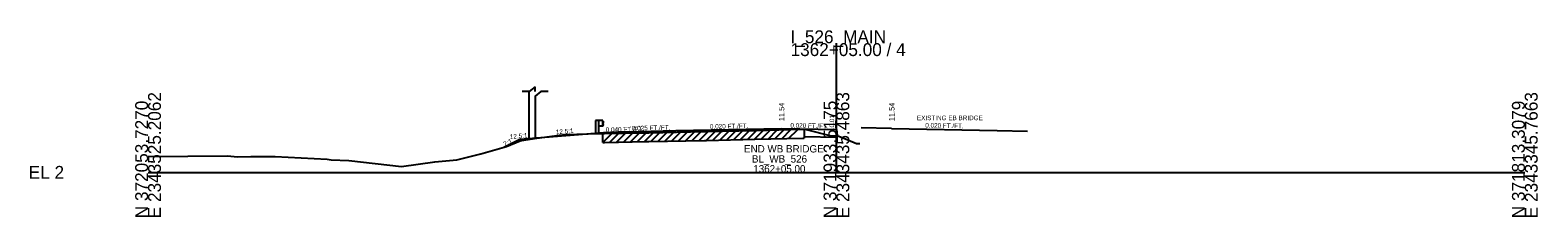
# Model space of a CAD drawing. Extents: x -170 to 2527928, y -10 to 1619750.
# Drawn here: x -25.7 to 302.8, y 7490.3 to 7531 of the extents above; entities that cross this region are included whole.
import ezdxf

# ---------------------------------------------------------------- set-up
doc = ezdxf.new("R2010")
doc.units = 0
for name, color, linetype in [('Default', 7, 'Continuous'), ('RD_GPK_XS_Cell', 7, 'Continuous'), ('RD_PD_NOISE-WALL-GM', 7, 'Continuous'), ('RD_PD_WallFill', 7, 'Continuous'), ('RD_XS_Base', 7, 'Continuous'), ('RD_XS_Bridge', 7, 'Continuous'), ('RD_XS_EarthShd', 7, 'Continuous'), ('RD_XS_ExGround', 7, 'Continuous'), ('RD_XS_ExPaveRet', 7, 'Continuous'), ('RD_XS_GR', 7, 'Continuous'), ('RD_XS_Pave', 7, 'Continuous'), ('RD_XS_PaveShd', 7, 'Continuous'), ('RD_XS_TieSlope', 7, 'Continuous'), ('RD_XS_TX_Elev_EX', 7, 'Continuous'), ('RD_XS_TX_Slope', 7, 'Continuous'), ('RD_XS_TX_Station', 7, 'Continuous')]:
    doc.layers.add(name, color=color, linetype=linetype)

msp = doc.modelspace()

# ---------------------------------------------------------------- linework, layer by layer
at = {"layer": 'Default'}
for p, q in [((83.08, 7517.63), (81.49, 7517.63)), ((84.33, 7518.66), (83.08, 7517.63)), ((84.33, 7517.63), (84.33, 7518.66)), ((85.58, 7517.63), (84.33, 7516.6)), ((87.17, 7517.63), (85.58, 7517.63))]:
    msp.add_line(p, q, dxfattribs=at)
at = {"layer": 'RD_GPK_XS_Cell'}
for p, q in [((150, 7500), (150, 7528.13)), ((0, 7500), (150, 7500)), ((150, 7500), (300, 7500))]:
    msp.add_line(p, q, dxfattribs=at)
at = {"layer": 'RD_PD_NOISE-WALL-GM'}
for p, q in [((82.95, 7517.63), (82.95, 7507.31)), ((84.45, 7507.43), (84.45, 7516.7))]:
    msp.add_line(p, q, dxfattribs=at)
at = {"layer": 'RD_PD_WallFill'}
msp.add_line((150, 7509.3), (150.18, 7508.02), dxfattribs=at)
at = {"layer": 'RD_XS_Base'}
for p, q in [((99.27, 7508.44), (99.27, 7508.62)), ((143, 7507.8), (150, 7507.66)), ((150, 7507.66), (150, 7509.3))]:
    msp.add_line(p, q, dxfattribs=at)
at = {"layer": 'RD_XS_Bridge'}
for p, q in [((162, 7509.54), (155.36, 7509.67)), ((162, 7509.54), (185, 7509.08)), ((185, 7509.08), (191.64, 7508.95))]:
    msp.add_line(p, q, dxfattribs=at)
at = {"layer": 'RD_XS_EarthShd'}
msp.add_line((99.27, 7508.62), (80.99, 7507.15), dxfattribs=at)
at = {"layer": 'RD_XS_ExGround'}
msp.add_lwpolyline([(0, 7503.46), (17.31, 7503.59), (19.49, 7503.41), (22.42, 7503.44), (24.23, 7503.47), (27.68, 7503.44), (39.06, 7502.86), (39.9, 7502.69), (43.77, 7502.58), (55.24, 7501.28), (62.48, 7502.27), (67.29, 7502.7), (72.49, 7504), (78.13, 7505.6), (81.07, 7506.86), (81.89, 7506.98), (84.72, 7507.47), (89.65, 7508.13), (90.96, 7508.21), (98.39, 7508.45), (99.09, 7508.44), (99.43, 7508.45), (108.54, 7508.61), (109.1, 7508.62), (121.24, 7508.87), (121.66, 7508.88), (132.22, 7509.1), (142.71, 7509.37), (143, 7509.38), (143.4, 7509.33), (148.84, 7507.96), (150.18, 7508.02), (152.46, 7507.08), (154.34, 7506.27), (154.89, 7506.31), (155.13, 7506.29)], dxfattribs=at)
at = {"layer": 'RD_XS_ExPaveRet'}
for p, q in [((99.09, 7506.52), (101.04, 7508.47)), ((99.09, 7506.52), (99.09, 7508.44)), ((100.59, 7506.55), (102.55, 7508.5)), ((102.09, 7506.58), (104.05, 7508.53)), ((103.59, 7506.6), (105.55, 7508.55)), ((105.09, 7506.63), (107.05, 7508.58)), ((106.59, 7506.66), (108.55, 7508.61)), ((108.09, 7506.68), (110.05, 7508.64)), ((109.59, 7506.71), (111.55, 7508.67)), ((111.09, 7506.74), (113.05, 7508.7)), ((112.59, 7506.77), (114.55, 7508.73)), ((114.09, 7506.81), (116.05, 7508.76)), ((115.59, 7506.84), (117.55, 7508.79)), ((117.09, 7506.87), (119.05, 7508.83)), ((118.59, 7506.9), (120.55, 7508.86)), ((120.09, 7506.93), (122.05, 7508.89)), ((121.59, 7506.96), (123.55, 7508.92)), ((121.66, 7506.96), (132.22, 7507.19)), ((123.09, 7506.99), (125.05, 7508.95)), ((124.59, 7507.03), (126.55, 7508.98)), ((126.09, 7507.06), (128.05, 7509.02)), ((127.59, 7507.09), (129.55, 7509.05)), ((129.09, 7507.12), (131.05, 7509.08)), ((130.59, 7507.15), (132.55, 7509.11)), ((132.09, 7507.18), (134.06, 7509.15)), ((132.22, 7507.19), (142.71, 7507.45)), ((133.59, 7507.22), (135.56, 7509.19)), ((135.09, 7507.26), (137.06, 7509.23)), ((136.59, 7507.3), (138.56, 7509.26)), ((138.09, 7507.33), (140.06, 7509.3)), ((139.59, 7507.37), (141.56, 7509.34)), ((142.71, 7507.45), (143, 7507.46)), ((143, 7509.38), (143, 7507.46)), ((99.09, 7506.52), (99.43, 7506.53)), ((99.43, 7506.53), (108.54, 7506.69)), ((108.54, 7506.69), (109.1, 7506.7)), ((109.1, 7506.7), (121.24, 7506.96)), ((121.24, 7506.96), (121.66, 7506.96))]:
    msp.add_line(p, q, dxfattribs=at)
at = {"layer": 'RD_XS_GR'}
for p, q in [((98.18, 7511.26), (97.51, 7511.26)), ((97.51, 7511.26), (97.51, 7508.46)), ((99.09, 7511.26), (98.18, 7511.26)), ((98.18, 7511.26), (98.18, 7508.51)), ((99.09, 7510.09), (99.09, 7511.26)), ((99.09, 7511.18), (99.26, 7510.98)), ((99.26, 7510.93), (99.09, 7510.73)), ((99.26, 7510.41), (99.09, 7510.61)), ((99.09, 7510.16), (99.26, 7510.36)), ((99.26, 7510.98), (99.26, 7510.93)), ((99.26, 7510.36), (99.26, 7510.41)), ((99.09, 7510.09), (98.18, 7510.09))]:
    msp.add_line(p, q, dxfattribs=at)
at = {"layer": 'RD_XS_Pave'}
for p, q in [((104, 7508.8), (115, 7509.08)), ((115, 7509.08), (138, 7509.54))]:
    msp.add_line(p, q, dxfattribs=at)
at = {"layer": 'RD_XS_PaveShd'}
msp.add_line((138, 7509.54), (150, 7509.3), dxfattribs=at)
msp.add_lwpolyline([(104, 7508.8), (99.27, 7508.62)], dxfattribs=at)
at = {"layer": 'RD_XS_TieSlope'}
for p, q in [((80.99, 7507.15), (77.56, 7505.44)), ((150, 7509.3), (150, 7508.01))]:
    msp.add_line(p, q, dxfattribs=at)

# ---------------------------------------------------------------- texts
at = {"layer": 'RD_GPK_XS_Cell'}
for s, p in [('I_526_MAIN', (140, 7528.13)), ('1362+05.00 / 4', (140, 7525.33)), ('EL 2', (-26, 7498.6))]:
    msp.add_text(s, height=2.8, dxfattribs=at).set_placement(p)
for s, p in [('E 2343525.2062', (2.8, 7490)), ('E 2343435.4863', (152.8, 7490)), ('E 2343345.7663', (302.8, 7490)), ('N 372053.7270', (0, 7490)), ('N 371933.5175', (150, 7490)), ('N 371813.3079', (300, 7490))]:
    msp.add_text(s, height=2.8, rotation=90, dxfattribs=at).set_placement(p)
at = {"layer": 'RD_XS_Bridge'}
msp.add_text('EXISTING EB BRIDGE', height=1, dxfattribs=at).set_placement((167.55, 7511.36))
at = {"layer": 'RD_XS_TX_Elev_EX'}
msp.add_text('10.01', height=1, rotation=90, dxfattribs=at).set_placement((149.5, 7509.01))
at = {"layer": 'RD_XS_TX_Slope'}
for s, rotation, p in [('0.025 FT./FT.', 1.4321, (105.44, 7509.09)), ('0.020 FT./FT.', 1.1458, (122.44, 7509.48)), ('0.020 FT./FT.', 358.8542, (139.95, 7509.75)), ('0.020 FT./FT.', 358.8542, (169.35, 7509.77)), ('2:1', 27.1209, (77.74, 7505.66)), ('12.5:1', 4.5739, (78.88, 7507.27)), ('12.5:1', 4.5739, (88.91, 7508.28)), ('0.040 FT./FT.', 1.4321, (99.74, 7508.78))]:
    msp.add_text(s, height=1, rotation=rotation, dxfattribs=at).set_placement(p)
at = {"layer": 'RD_XS_TX_Station'}
for p in [(138.66, 7510.71), (162.66, 7510.71)]:
    msp.add_text(' 11.54', height=1.2, rotation=90, dxfattribs=at).set_placement(p)
for s, p in [('END WB BRIDGE', (129.86, 7504.33)), ('BL_WB_526', (131.58, 7502.12)), ('1362+05.00', (131.88, 7499.97))]:
    msp.add_text(s, height=1.6, dxfattribs=at).set_placement(p)

doc.saveas('drawing.dxf')
